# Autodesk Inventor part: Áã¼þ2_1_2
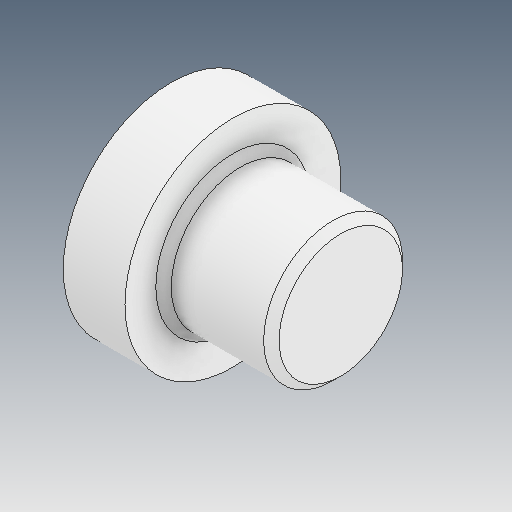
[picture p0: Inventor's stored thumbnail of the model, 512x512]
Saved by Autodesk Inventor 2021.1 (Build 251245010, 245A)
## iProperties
Created: 2021-05
Part Number: Áã¼þ2_1_2
Material: Ogólny
Document SubType Name: Modeling
Designer: user
Density: 1 g/cm^3
Appearance: Domyślna
Author: user
Revision Number: ÈÎºÎ
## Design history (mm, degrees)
feature "ÊäÈë1"
node "Bryła1"
